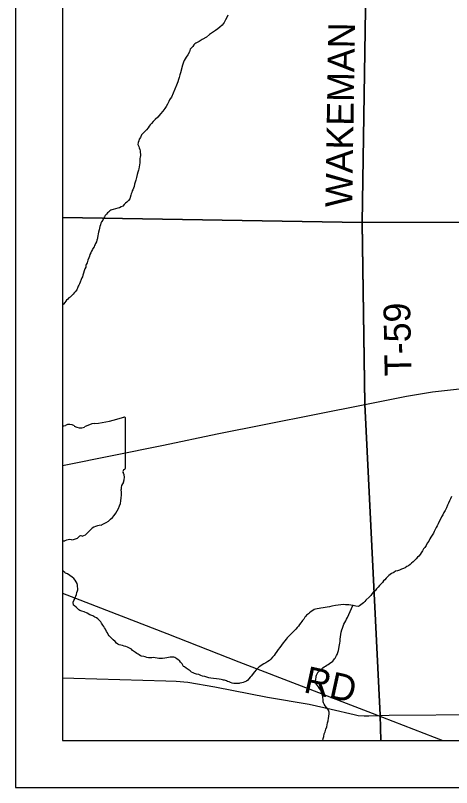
# Model space of a CAD drawing. Extents: x 0 to 34, y 0 to 22.
# Drawn here: x 2 to 2.927, y 14 to 15.642 of the extents above; entities that cross this region are included whole.
import ezdxf

# ---------------------------------------------------------------- set-up
doc = ezdxf.new("R2010")
doc.units = 0
for name, color, linetype in [('Default', 7, 'Continuous'), ('GM_X_Corporation', 7, 'Continuous'), ('GM_X_County_Road', 7, 'Continuous'), ('GM_X_County_Road_Text', 7, 'Continuous'), ('GM_X_Minor_River', 7, 'Continuous'), ('GM_X_Rail_Line', 7, 'Continuous'), ('GM_X_State_Route', 7, 'Continuous'), ('GM_X_Township_Road', 7, 'Continuous'), ('GM_X_Township_Road_Text', 7, 'Continuous'), ('SH_Data', 7, 'Continuous')]:
    doc.layers.add(name, color=color, linetype=linetype)

msp = doc.modelspace()

# ---------------------------------------------------------------- linework, layer by layer
at = {"layer": 'Default'}
msp.add_line((2.1, 14.7694), (2.1, 14.5239), dxfattribs=at)
msp.add_lwpolyline([(2.2337, 14.6799), (2.2337, 14.6799), (2.2337, 14.6799), (2.2337, 14.7847)], dxfattribs=at)
for centre, radius, start, end in [((2.1398, 15.0524), 0.2796, 275.8445, 288.9065), ((2.2308, 14.785), 0.00294, 355.0978, 97.738), ((2.1022, 14.7776), 0.00855, 255.06, 297.1024), ((2.1148, 14.7545), 0.0178, 54.4667, 119.1411), ((2.1377, 14.7862), 0.0214, 233.8562, 294.8282), ((2.1754, 14.7185), 0.0563, 97.3462, 120.7689), ((2.233, 14.6722), 0.00454, 107.944, 210.337), ((2.2041, 14.659), 0.0273, 340.033, 23.6496), ((2.2306, 14.6795), 0.00314, 289.6038, 7.7341), ((2.2442, 14.6361), 0.0198, 136.8065, 186.9296), ((2.1554, 14.6227), 0.0699, 292.3089, 8.9858), ((2.1849, 14.5199), 0.0383, 94.4031, 142.5768), ((2.1196, 14.5485), 0.0214, 268.777, 315.5493), ((2.139, 14.5291), 0.00601, 65.7517, 132.6484), ((2.1364, 14.5566), 0.0226, 282.8732, 323.2771), ((2.0935, 14.5635), 0.0401, 279.2596, 286.2918), ((2.1167, 14.4943), 0.0329, 85.6951, 111.21)]:
    msp.add_arc(centre, radius, start, end, dxfattribs=at)
at = {"layer": 'GM_X_Corporation'}
for points in [[(2.1, 20.2456), (2.1, 14.1), (8.0383, 14.1), (8.035, 14.2498), (8.0349, 14.2572), (8.0297, 14.4963), (8.0262, 14.6555), (8.0153, 15.2273), (7.992, 16.4534)], [(2.7477, 15.8824), (2.7366, 15.2014), (3.5209, 15.2041), (3.6901, 15.2048), (3.6901, 15.7256)]]:
    msp.add_lwpolyline(points, dxfattribs=at)
for points in [[(2.1, 20.2456), (2.1, 15.2121), (2.7366, 15.2014), (2.7477, 15.8824), (2.7304, 16.9599), (2.7184, 17.7156), (2.7024, 18.7188), (2.6883, 19.5017), (2.6825, 20.2316), (2.6344, 20.2324), (2.5847, 20.2334), (2.535, 20.2346), (2.5164, 20.2351), (2.4604, 20.2364), (2.3921, 20.2383), (2.333, 20.2398), (2.2833, 20.2411), (2.246, 20.2419), (2.187, 20.2434), (2.1124, 20.2453)], [(3.6901, 15.2048), (3.5209, 15.2041), (2.7366, 15.2014), (2.7422, 14.8151), (2.7753, 14.1537), (2.7761, 14.1), (8.0383, 14.1), (8.035, 14.2498), (8.0349, 14.2572), (8.0297, 14.4963), (8.0262, 14.6555), (8.0153, 15.2273), (6.9496, 15.2134), (6.7394, 15.212), (6.1026, 15.2145), (5.9099, 15.2138), (5.9099, 15.0085), (3.6901, 15.0085)], [(2.1, 15.2121), (2.1, 14.1), (2.7761, 14.1), (2.7753, 14.1537), (2.7422, 14.8151), (2.7366, 15.2014)]]:
    msp.add_lwpolyline(points, close=True, dxfattribs=at)
at = {"layer": 'GM_X_County_Road'}
for points in [[(2.1, 14.2335), (2.1238, 14.2328), (2.3196, 14.2267), (2.3413, 14.2263), (2.3663, 14.2244), (2.4234, 14.2139), (2.5357, 14.1925), (2.6243, 14.1776), (2.6707, 14.1669), (2.7195, 14.1551), (2.7282, 14.153), (2.7411, 14.1524), (2.7512, 14.1526)], [(2.7512, 14.1526), (2.7755, 14.1532), (2.7942, 14.1536), (2.9934, 14.1556), (3.0302, 14.1558), (3.0685, 14.1556), (3.1205, 14.1545), (3.438, 14.1396)]]:
    msp.add_lwpolyline(points, dxfattribs=at)
at = {"layer": 'GM_X_Minor_River'}
for points in [[(2.4515, 15.6428), (2.4491, 15.6379), (2.446, 15.633), (2.4433, 15.6269), (2.4391, 15.6212), (2.4344, 15.6171), (2.4302, 15.6138), (2.4249, 15.61), (2.4187, 15.6055), (2.4122, 15.6018), (2.4061, 15.5958), (2.3965, 15.5906), (2.3904, 15.5869), (2.3858, 15.5846), (2.3831, 15.5831), (2.3812, 15.5816), (2.3793, 15.5794), (2.3769, 15.5764), (2.3742, 15.573), (2.3715, 15.5707), (2.3696, 15.5647), (2.3665, 15.5582), (2.363, 15.5533), (2.3607, 15.55), (2.3587, 15.5462), (2.3568, 15.5428), (2.3548, 15.536), (2.3504, 15.52), (2.3492, 15.5155), (2.3476, 15.5102), (2.3464, 15.506), (2.3449, 15.5011), (2.3421, 15.4939), (2.339, 15.4856), (2.3351, 15.4769), (2.3315, 15.4686), (2.3285, 15.4648), (2.3273, 15.4625), (2.3261, 15.4591), (2.3234, 15.4531), (2.3199, 15.4482), (2.3172, 15.444), (2.3133, 15.4388), (2.3083, 15.4327), (2.3025, 15.426), (2.2971, 15.4207)], [(2.2971, 15.4207), (2.2929, 15.4166), (2.289, 15.4121), (2.2864, 15.4091), (2.284, 15.4064), (2.2817, 15.4034), (2.2782, 15.3989), (2.2748, 15.3951), (2.2725, 15.3932), (2.2702, 15.3906), (2.2679, 15.388), (2.2655, 15.3823), (2.2632, 15.3789), (2.262, 15.3751), (2.2608, 15.3721), (2.2604, 15.3675), (2.2619, 15.3633), (2.263, 15.3607), (2.2641, 15.3569), (2.2648, 15.3538), (2.2651, 15.3508), (2.2655, 15.3473), (2.2654, 15.3443), (2.265, 15.3409), (2.2646, 15.3375), (2.2641, 15.3306), (2.2641, 15.3284), (2.2637, 15.3246), (2.2629, 15.3204), (2.262, 15.3162), (2.2612, 15.3128), (2.2601, 15.309), (2.2589, 15.3037), (2.2573, 15.2976), (2.2557, 15.292), (2.2545, 15.2878), (2.2537, 15.2855), (2.2529, 15.2833), (2.2521, 15.2783), (2.2497, 15.2715), (2.2482, 15.2692), (2.2474, 15.2655), (2.2458, 15.2624), (2.2454, 15.2598), (2.243, 15.2522), (2.2403, 15.2484), (2.2369, 15.245), (2.2338, 15.2428), (2.2311, 15.2398), (2.228, 15.2368), (2.2246, 15.2349), (2.2211, 15.2331), (2.2173, 15.232), (2.2074, 15.2294), (2.2047, 15.2287), (2.2028, 15.228), (2.2009, 15.2268), (2.1978, 15.2238), (2.1955, 15.222), (2.1932, 15.2193), (2.1909, 15.2163), (2.189, 15.2137), (2.1874, 15.211), (2.1855, 15.2069), (2.1831, 15.2031), (2.1816, 15.2005), (2.1804, 15.1967), (2.1792, 15.1929), (2.1784, 15.1899), (2.1776, 15.1861), (2.1768, 15.1811), (2.176, 15.1777), (2.1752, 15.1732), (2.1744, 15.1701), (2.174, 15.1679), (2.1736, 15.166), (2.1728, 15.1641), (2.172, 15.1607), (2.1704, 15.1573), (2.1693, 15.1546), (2.1681, 15.1527), (2.1673, 15.1501), (2.1646, 15.1463), (2.1638, 15.1444), (2.1619, 15.1406), (2.1603, 15.1369), (2.1584, 15.1338), (2.1572, 15.1304), (2.1556, 15.1263), (2.154, 15.1217), (2.1521, 15.1161), (2.1505, 15.1127), (2.1497, 15.1108), (2.1493, 15.1066), (2.1477, 15.1032), (2.1462, 15.0986), (2.1446, 15.0937), (2.1434, 15.0899), (2.1422, 15.0861), (2.141, 15.0839), (2.1363, 15.071)], [(2.1363, 15.071), (2.1348, 15.0684), (2.1336, 15.0661), (2.1324, 15.0642), (2.1301, 15.0585), (2.127, 15.054), (2.1247, 15.0518), (2.1228, 15.0495), (2.1208, 15.0469), (2.1185, 15.045), (2.1162, 15.0431), (2.1135, 15.0413), (2.1112, 15.0386), (2.1085, 15.0364), (2.107, 15.0345), (2.1051, 15.0319), (2.102, 15.0277), (2.1, 15.0256)], [(2.9269, 14.6192), (2.9246, 14.6143), (2.9226, 14.6098), (2.9203, 14.6049), (2.9179, 14.6003), (2.9156, 14.5947), (2.9129, 14.5894), (2.9105, 14.5852), (2.9082, 14.5803), (2.9055, 14.5754), (2.8981, 14.561), (2.8961, 14.5569), (2.8942, 14.5527), (2.8922, 14.5486), (2.8899, 14.5448), (2.888, 14.541), (2.8856, 14.5369), (2.8829, 14.5327), (2.8806, 14.5286), (2.8782, 14.5237), (2.8752, 14.5199), (2.8724, 14.515), (2.8697, 14.5108), (2.8674, 14.5074), (2.8651, 14.5033), (2.8624, 14.4995), (2.8597, 14.4957), (2.857, 14.4924), (2.8543, 14.4897), (2.8516, 14.4863), (2.8485, 14.4833), (2.845, 14.48), (2.8419, 14.477), (2.8385, 14.4743), (2.835, 14.4717)], [(2.835, 14.4717), (2.8316, 14.4699), (2.8281, 14.4676), (2.8243, 14.4661), (2.8201, 14.4643), (2.8159, 14.4624), (2.8117, 14.461), (2.8075, 14.4599), (2.8037, 14.4573), (2.7991, 14.4554), (2.7964, 14.4532), (2.7937, 14.4509), (2.7907, 14.4483), (2.788, 14.4453), (2.7849, 14.4419), (2.7822, 14.4393), (2.7799, 14.4363), (2.7768, 14.4329), (2.7737, 14.4295), (2.7706, 14.4265), (2.7672, 14.4224), (2.7641, 14.4186), (2.761, 14.416), (2.7583, 14.4126), (2.7552, 14.4084), (2.7525, 14.4058), (2.7448, 14.3983), (2.7425, 14.396), (2.7394, 14.393), (2.7367, 14.3904), (2.7337, 14.3885), (2.731, 14.3867), (2.7283, 14.3852), (2.723, 14.386), (2.7177, 14.3872), (2.7128, 14.388), (2.7086, 14.3885), (2.7063, 14.3885), (2.7044, 14.3889), (2.7014, 14.3889), (2.6972, 14.389), (2.6915, 14.3887), (2.6854, 14.388), (2.6801, 14.3869), (2.6724, 14.3858), (2.6671, 14.3844), (2.6622, 14.3833), (2.6583, 14.3826), (2.6538, 14.3819), (2.6488, 14.3812), (2.6378, 14.3794), (2.6351, 14.3787), (2.6317, 14.3768), (2.6282, 14.3742), (2.6248, 14.3716), (2.6228, 14.3697), (2.6205, 14.3678), (2.6186, 14.3663), (2.6171, 14.3645), (2.6151, 14.3622), (2.6128, 14.358), (2.6101, 14.355), (2.6082, 14.3528), (2.6063, 14.3501), (2.6039, 14.3467), (2.6012, 14.3434), (2.5985, 14.3404), (2.5955, 14.337), (2.5928, 14.334), (2.5897, 14.3306), (2.5862, 14.3272), (2.582, 14.3231), (2.5797, 14.3204), (2.5774, 14.3186), (2.5754, 14.3159), (2.5727, 14.3122), (2.5692, 14.3076), (2.5654, 14.3027), (2.5615, 14.2978), (2.5584, 14.2937), (2.5553, 14.2892), (2.5522, 14.2846), (2.5495, 14.2805), (2.5465, 14.2771), (2.543, 14.273), (2.5395, 14.2704), (2.5365, 14.2681), (2.5322, 14.2655), (2.528, 14.2629), (2.5246, 14.261), (2.5211, 14.2588), (2.5181, 14.2565), (2.5146, 14.2535), (2.5112, 14.2502), (2.5081, 14.2464), (2.5011, 14.237), (2.4988, 14.2344), (2.4961, 14.231), (2.4938, 14.2283), (2.4907, 14.2265), (2.4877, 14.225)], [(2.1723, 14.3606), (2.1685, 14.3625), (2.1643, 14.3649), (2.1583, 14.3676), (2.1526, 14.3711), (2.1458, 14.3734), (2.1409, 14.3754), (2.1371, 14.3766), (2.1345, 14.3778), (2.1311, 14.3812), (2.1288, 14.3839), (2.1254, 14.3862), (2.1236, 14.3878), (2.1229, 14.3946), (2.1244, 14.3976), (2.126, 14.401), (2.1272, 14.4041), (2.1283, 14.4067), (2.1295, 14.4109), (2.1307, 14.415), (2.1319, 14.4185), (2.1323, 14.4204), (2.1323, 14.4238), (2.132, 14.4272), (2.1317, 14.4306), (2.1309, 14.434), (2.1272, 14.4413), (2.1239, 14.4444), (2.1205, 14.4471), (2.1156, 14.451), (2.1103, 14.4544), (2.1065, 14.456), (2.1046, 14.4572), (2.1016, 14.4602), (2.1, 14.4613)], [(2.6531, 14.1), (2.6539, 14.1041), (2.655, 14.1086), (2.6563, 14.1139), (2.6582, 14.1185), (2.6598, 14.1238), (2.6614, 14.1291), (2.6626, 14.1332), (2.6634, 14.1374), (2.6642, 14.1419), (2.665, 14.1473), (2.6658, 14.1514), (2.6663, 14.1575), (2.6667, 14.1605), (2.666, 14.1624), (2.6652, 14.1644), (2.6637, 14.167), (2.6611, 14.1705), (2.6581, 14.1739), (2.6559, 14.1774), (2.6544, 14.1801), (2.654, 14.1823), (2.6537, 14.1843), (2.6537, 14.1881), (2.6534, 14.1907), (2.653, 14.1938), (2.6516, 14.1983), (2.6505, 14.2018), (2.6494, 14.2048), (2.6479, 14.2075), (2.6464, 14.2106), (2.6442, 14.214), (2.6419, 14.2171), (2.6397, 14.2198), (2.6382, 14.2217), (2.6374, 14.224), (2.6378, 14.227), (2.6383, 14.2308), (2.6387, 14.2346), (2.6391, 14.2369), (2.6399, 14.2391), (2.6415, 14.2433), (2.6434, 14.2459), (2.6453, 14.2478), (2.6472, 14.2497), (2.6511, 14.2527), (2.6534, 14.2546), (2.6561, 14.2564), (2.6591, 14.2583), (2.6618, 14.2602), (2.6645, 14.262), (2.6672, 14.2639), (2.6741, 14.2691), (2.6764, 14.2714), (2.6783, 14.2737), (2.6795, 14.2755), (2.681, 14.2778), (2.6822, 14.2805), (2.6838, 14.2831), (2.6845, 14.2854), (2.6853, 14.2873), (2.6861, 14.2895), (2.6865, 14.2918), (2.6869, 14.2948), (2.6881, 14.2998), (2.6889, 14.3036), (2.6894, 14.3074), (2.6898, 14.3111), (2.6902, 14.3153), (2.691, 14.3203), (2.6915, 14.3256), (2.6923, 14.3305), (2.6935, 14.3354), (2.6947, 14.3392), (2.6963, 14.343), (2.6978, 14.3475), (2.7002, 14.3509), (2.7017, 14.3543), (2.7037, 14.3581), (2.7056, 14.3615), (2.7167, 14.3874)], [(2.4877, 14.225), (2.4842, 14.2235), (2.4812, 14.2224), (2.477, 14.2217), (2.4751, 14.2213), (2.4732, 14.2214), (2.4701, 14.221), (2.4667, 14.221), (2.4637, 14.2215), (2.4603, 14.2223), (2.4569, 14.2234), (2.4538, 14.2246), (2.4508, 14.2258), (2.4485, 14.2266), (2.4463, 14.2274), (2.444, 14.2282), (2.4421, 14.2282), (2.4398, 14.229), (2.4372, 14.2298), (2.4326, 14.2306), (2.4269, 14.2314), (2.4208, 14.2319), (2.4151, 14.2323), (2.411, 14.2335), (2.4064, 14.2347), (2.4023, 14.2363), (2.3973, 14.2371), (2.3939, 14.2386), (2.3894, 14.2402), (2.3848, 14.2414), (2.3803, 14.2426), (2.3773, 14.2438), (2.3743, 14.2457), (2.3712, 14.248), (2.3671, 14.2507), (2.3626, 14.2542), (2.3592, 14.2565), (2.3569, 14.2577), (2.3543, 14.2634), (2.3509, 14.2669), (2.3483, 14.27), (2.3457, 14.2719), (2.343, 14.2738), (2.3408, 14.2754), (2.3385, 14.2765), (2.3362, 14.2773), (2.334, 14.2773), (2.3317, 14.2774), (2.3286, 14.277), (2.3252, 14.2767), (2.3214, 14.276), (2.3172, 14.2753), (2.3123, 14.2746), (2.3081, 14.2742), (2.3047, 14.2747), (2.3012, 14.2755), (2.2971, 14.2759), (2.2933, 14.2763), (2.2895, 14.276), (2.2864, 14.2756), (2.283, 14.2757), (2.2792, 14.2765), (2.2758, 14.2777), (2.2728, 14.2788), (2.2678, 14.2796), (2.2656, 14.2804), (2.2629, 14.2824), (2.2607, 14.2835), (2.258, 14.2851), (2.255, 14.287), (2.2531, 14.2886), (2.2509, 14.2901), (2.249, 14.2913), (2.2463, 14.294), (2.2437, 14.2959), (2.2411, 14.2971), (2.238, 14.2986), (2.2346, 14.3002), (2.2312, 14.301), (2.2278, 14.3018), (2.224, 14.3026), (2.2202, 14.3034), (2.2172, 14.3049), (2.2146, 14.3069), (2.212, 14.3107), (2.2078, 14.3142), (2.1988, 14.3223), (2.1969, 14.3257), (2.1954, 14.3288), (2.1936, 14.3322), (2.1914, 14.3368), (2.1895, 14.3399), (2.188, 14.3422), (2.1858, 14.3456), (2.1843, 14.3475), (2.1828, 14.3494), (2.1813, 14.3521), (2.1794, 14.3544), (2.1772, 14.3567), (2.1749, 14.3587), (2.1723, 14.3606)]]:
    msp.add_lwpolyline(points, dxfattribs=at)
at = {"layer": 'GM_X_Rail_Line'}
msp.add_lwpolyline([(2.1, 14.4134), (2.1277, 14.4027), (2.3218, 14.3275), (2.4747, 14.2674), (2.7578, 14.1583), (2.8897, 14.1072), (2.9084, 14.1)], dxfattribs=at)
at = {"layer": 'GM_X_State_Route'}
msp.add_lwpolyline([(2.1, 14.6851), (2.3144, 14.728), (2.4286, 14.752), (2.7425, 14.8145), (2.8311, 14.8324), (2.8864, 14.8416), (2.937, 14.8474), (2.9895, 14.8488), (3.0376, 14.8469), (3.1012, 14.8401), (3.1496, 14.8296), (3.1902, 14.8183), (3.2378, 14.8024), (3.354, 14.7588), (3.4295, 14.7299), (3.4844, 14.7097), (3.6309, 14.6542), (3.7935, 14.5941), (4.0411, 14.4997)], dxfattribs=at)
at = {"layer": 'GM_X_Township_Road'}
for points in [[(2.7371, 15.2138), (2.7479, 15.8819), (2.7307, 16.9594), (2.7186, 17.715)], [(2.7425, 14.8145), (2.7369, 15.2009), (2.7371, 15.2138)]]:
    msp.add_lwpolyline(points, dxfattribs=at)
at = {"layer": 'SH_Data'}
for p, q in [((2, 21), (2, 14)), ((2.1, 20.9), (2.1, 14.1)), ((2.1, 14.1), (8.9, 14.1)), ((2.1, 14.1), (2.1, 14.1)), ((2, 14), (9, 14))]:
    msp.add_line(p, q, dxfattribs=at)

# ---------------------------------------------------------------- texts
at = {"layer": 'GM_X_County_Road_Text'}
msp.add_text('RD', height=0.05682, rotation=347.6306, dxfattribs=at).set_placement((2.6101, 14.2031))
at = {"layer": 'GM_X_Township_Road_Text'}
for s, rotation, p in [('WAKEMAN', 89.0968, (2.7155, 15.2341)), ('T-59', 91.0617, (2.8415, 14.8756))]:
    msp.add_text(s, height=0.05682, rotation=rotation, dxfattribs=at).set_placement(p)

doc.saveas('drawing.dxf')
